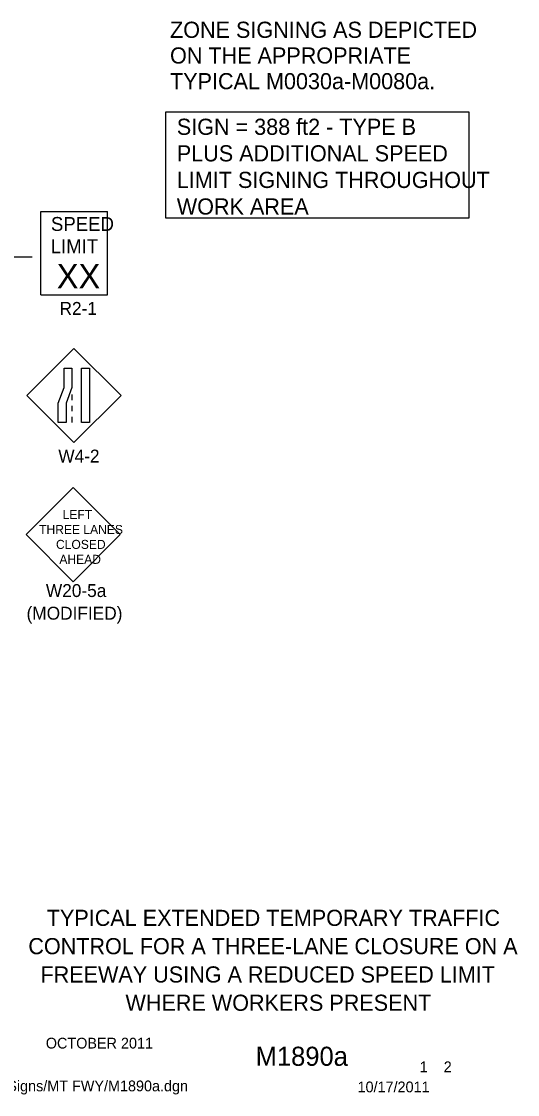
# Model space of a CAD drawing. Extents: x 16725 to 18475, y 5932 to 7023.
# Drawn here: x 17154 to 17440, y 5932 to 6550 of the extents above; entities that cross this region are included whole.
import ezdxf

# ---------------------------------------------------------------- set-up
doc = ezdxf.new("R2010")
doc.units = 0
for name, color, linetype in [('BORDER', 7, 'Continuous'), ('BORDER_SIGNAL_WO', 7, 'Continuous'), ('TRAFFIC_SIGNS_PR', 7, 'Continuous'), ('TYPICAL_TEXT_DIMEN_EX', 7, 'Continuous'), ('TYPICAL_TEXT_DIMEN_PR', 7, 'Continuous')]:
    doc.layers.add(name, color=color, linetype=linetype)

msp = doc.modelspace()

# ---------------------------------------------------------------- linework, layer by layer
at = {"layer": 'TRAFFIC_SIGNS_PR'}
for p, q in [((17165.49, 6440.42), (17203.94, 6440.42)), ((17165.49, 6392.36), (17165.49, 6440.42)), ((17203.94, 6392.36), (17203.94, 6440.42)), ((17165.49, 6392.36), (17203.94, 6392.36)), ((17184.54, 6361.62), (17157.39, 6334.46)), ((17211.69, 6334.46), (17184.54, 6361.62)), ((17157.39, 6334.46), (17184.54, 6307.31)), ((17183.29, 6334.96), (17183.29, 6331.76)), ((17184.54, 6307.31), (17211.69, 6334.46)), ((17183.29, 6328.56), (17183.29, 6325.36)), ((17183.29, 6322.16), (17183.29, 6318.96)), ((17184.05, 6281.53), (17156.89, 6254.37)), ((17211.2, 6254.37), (17184.05, 6281.53)), ((17156.89, 6254.37), (17184.05, 6227.22)), ((17184.05, 6227.22), (17211.2, 6254.37))]:
    msp.add_line(p, q, dxfattribs=at)
for points in [[(17183.29, 6350.2), (17183.29, 6339.02), (17179.95, 6330.14), (17179.95, 6318.96), (17175.45, 6318.96), (17175.45, 6330.14), (17178.8, 6339.02), (17178.8, 6350.2)], [(17193.43, 6350.2), (17193.43, 6318.96), (17188.93, 6318.96), (17188.93, 6350.2)]]:
    msp.add_lwpolyline(points, close=True, dxfattribs=at)
at = {"layer": 'TYPICAL_TEXT_DIMEN_EX'}
msp.add_lwpolyline([(17237.55, 6497.78), (17412.13, 6497.78), (17412.13, 6436.53), (17237.55, 6436.53)], close=True, dxfattribs=at)
at = {"layer": 'TYPICAL_TEXT_DIMEN_PR'}
msp.add_line((17060.93, 6414.41), (17160.46, 6414.41), dxfattribs=at)

# ---------------------------------------------------------------- texts
at = {"layer": 'BORDER'}
for s, p in [('TYPICAL EXTENDED TEMPORARY TRAFFIC', (17168.85, 6028.96)), ('CONTROL FOR A THREE-LANE CLOSURE ON A', (17158.22, 6012.66)), ('FREEWAY USING A REDUCED SPEED LIMIT', (17165.22, 5996.36)), ('WHERE WORKERS PRESENT', (17214.22, 5980.06))]:
    msp.add_text(s, height=9.3, dxfattribs=at).set_placement(p)
at = {"layer": 'BORDER_SIGNAL_WO'}
for s, height, p in [('    OCTOBER 2011', 6.2, (17159.08, 5958.34)), ('    M1890a   ', 11, (17272.86, 5948.38)), (' 1    2 ', 6.2, (17381.45, 5944.7)), ('PW RD/TS/Typicals/Signs/MT FWY/M1890a.dgn      ', 6.2, (17070.55, 5933.71)), ('10/17/2011', 6.2, (17347.93, 5933.13))]:
    msp.add_text(s, height=height, dxfattribs=at).set_placement(p)
at = {"layer": 'TRAFFIC_SIGNS_PR'}
for s, height, p in [('SPEED', 8.01, (17171.26, 6429.27)), ('LIMIT', 8.01, (17171.1, 6416.45)), ('XX', 14.048, (17174.61, 6396.12)), ('R2-1', 7.449, (17176.18, 6380.9)), ('W4-2', 7.44, (17175.5, 6295.87)), ('LEFT', 5.2, (17177.99, 6263.31)), ('THREE LANES', 5.2, (17164.44, 6254.71)), ('CLOSED', 5.2, (17174.17, 6246.11)), ('AHEAD', 5.2, (17176.11, 6237.51)), ('W20-5a', 7.44, (17168.35, 6218.4)), ('(MODIFIED)', 7.44, (17157.2, 6205.36))]:
    msp.add_text(s, height=height, dxfattribs=at).set_placement(p)
at = {"layer": 'TYPICAL_TEXT_DIMEN_EX'}
for s, p in [('ZONE SIGNING AS DEPICTED', (17239.88, 6540.47)), ('ON THE APPROPRIATE', (17239.88, 6525.67)), ('TYPICAL M0030a-M0080a.', (17239.88, 6510.87)), ('SIGN = 388 ft2 - TYPE B', (17243.78, 6484.6)), ('PLUS ADDITIONAL SPEED', (17243.78, 6469.3)), ('LIMIT SIGNING THROUGHOUT', (17243.78, 6454)), ('WORK AREA', (17243.78, 6438.7))]:
    msp.add_text(s, height=9.3, dxfattribs=at).set_placement(p)

doc.saveas('drawing.dxf')
